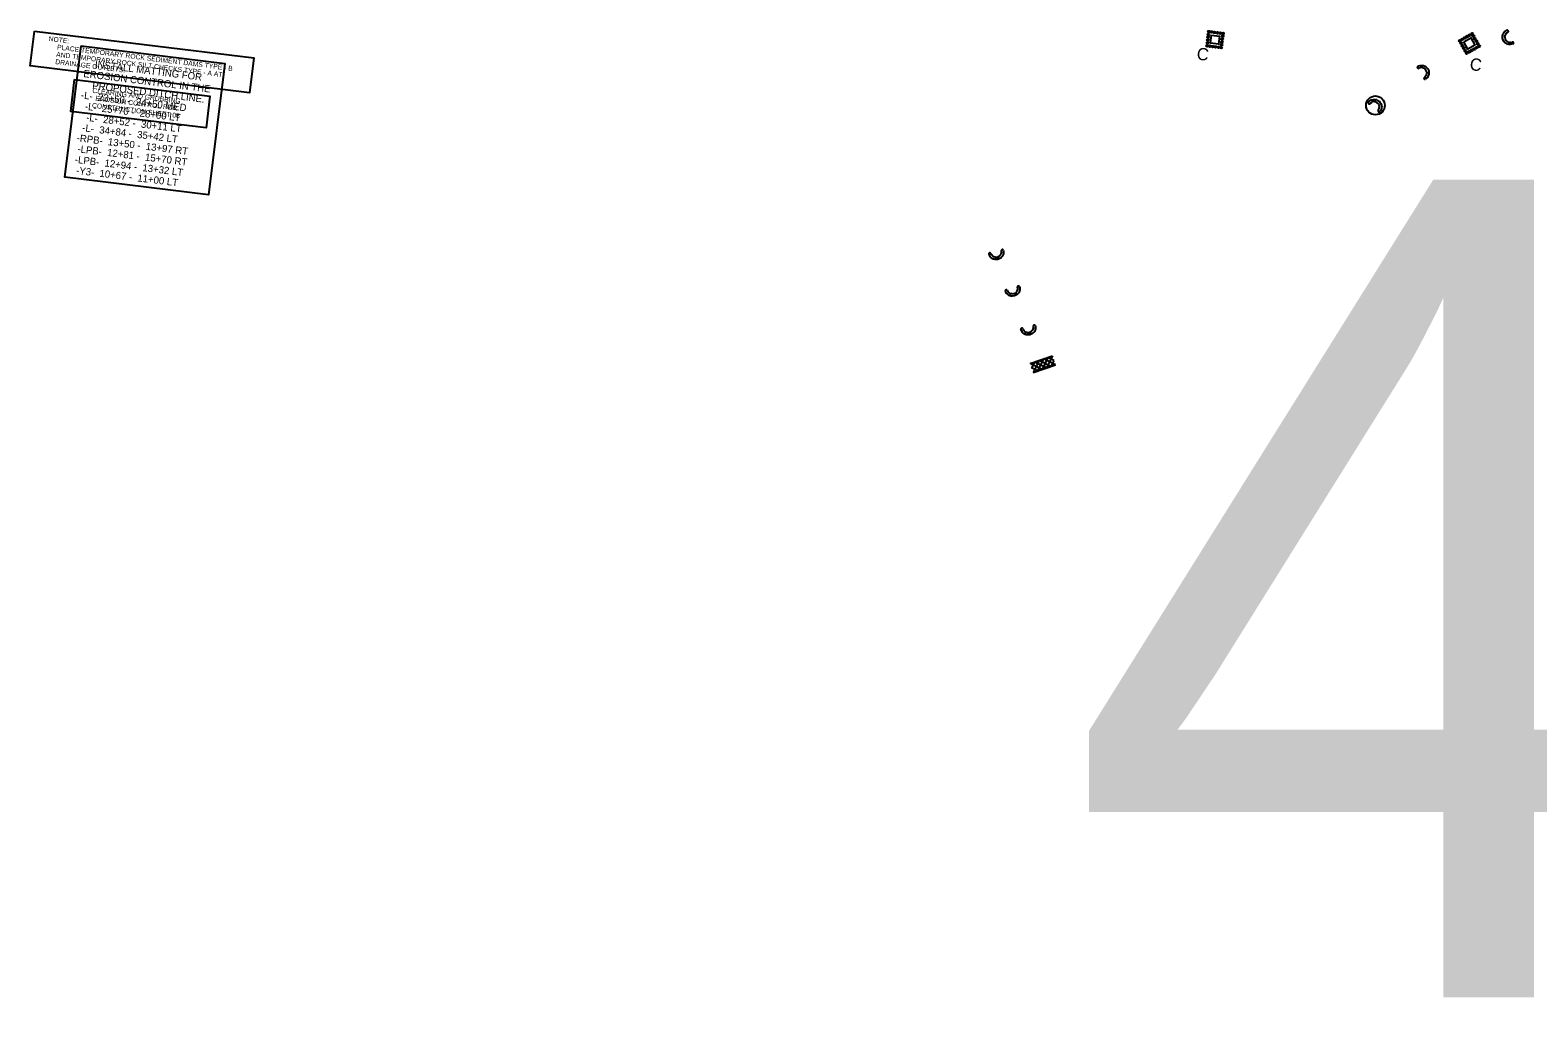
# Model space of a CAD drawing. Extents: x 2470000 to 2520000, y 340000 to 380000.
# Drawn here: x 2482139 to 2483984, y 364486 to 365683 of the extents above; entities that cross this region are included whole.
import ezdxf

# ---------------------------------------------------------------- set-up
doc = ezdxf.new("R2010")
doc.units = 0
for name, color, linetype in [('Coir Fiber Wattle Both CELL', 7, 'Continuous'), ('Coir Fiber Wattle with PAM Both CELL', 7, 'Continuous'), ('Construction Sheet Number Note CG CELL', 7, 'Continuous'), ('Matting in Proposed Ditchline Note Final CELL', 7, 'Continuous'), ('Prop Guardrail', 7, 'Continuous'), ('Prop Guardrail Anchor Unit CELL', 7, 'Continuous'), ('Prop Structure Anchor Unit CELL', 7, 'Continuous'), ('Rock Inlet Sediment Trap Type C CG CELL', 7, 'Continuous'), ('Rock Silt Check Type A Final CELL', 7, 'Continuous'), ('Scratch_Level_5', 7, 'Continuous'), ('Scratch_Level_6', 7, 'Continuous'), ('Sediment Dams and Silt Check Note CG CELL', 7, 'Continuous'), ('Wattle Final CELL', 7, 'Continuous')]:
    doc.layers.add(name, color=color, linetype=linetype)

# ---------------------------------------------------------------- blocks, each defined once
blk = doc.blocks.new('C3')
at = {"layer": 'Prop Guardrail'}
blk.add_text('C', height=0.3, dxfattribs=at).set_placement((-0.161, -0.136))
blk = doc.blocks.new('C2')
at = {"layer": 'Prop Guardrail Anchor Unit CELL'}
blk.add_text('C', height=0.3, dxfattribs=at).set_placement((-0.161, -0.136))
blk = doc.blocks.new('CGNT2')
at = {"layer": 'Sediment Dams and Silt Check Note CG CELL'}
blk.add_lwpolyline([(-2.704, 0.431), (2.704, 0.43125), (2.704, -0.43), (-2.704, -0.43)], close=True, dxfattribs=at)
for s, p in [('NOTE:', (-2.335, 0.231)), ('     PLACE TEMPORARY ROCK SEDIMENT DAMS TYPE - B', (-2.335, 0.05125)), ('     AND TEMPORARY ROCK SILT CHECKS TYPE - A AT', (-2.335, -0.129)), ('     DRAINAGE OUTLETS.', (-2.335, -0.309))]:
    blk.add_text(s, height=0.12, dxfattribs=at).set_placement(p)

msp = doc.modelspace()

# ---------------------------------------------------------------- linework, layer by layer
at = {"layer": 'Coir Fiber Wattle Both CELL'}
for p, q in [((2483943.2, 365674.5), (2483943.4, 365675.7)), ((2483943.2, 365674.5), (2483943.8, 365671.9)), ((2483943.5, 365676.8), (2483943.4, 365675.7)), ((2483943.5, 365676.8), (2483943.6, 365677)), ((2483944.4, 365678.2), (2483943.6, 365677)), ((2483943.8, 365671.9), (2483943.8, 365671.9)), ((2483943.8, 365671.9), (2483945.2, 365669.8)), ((2483945, 365679.2), (2483944.4, 365678.2)), ((2483945.6, 365679.6), (2483945, 365679.2)), ((2483945.2, 365669.8), (2483946.2, 365669.1)), ((2483946.9, 365680.5), (2483945.6, 365679.6)), ((2483946.2, 365669.1), (2483947.4, 365668.3)), ((2483947.4, 365668.3), (2483948.4, 365668.1)), ((2483948.4, 365668.1), (2483949.9, 365667.9)), ((2483950.2, 365668), (2483949.9, 365667.9)), ((2483950.2, 365668), (2483952, 365668.4)), ((2483839.7, 365637), (2483838, 365636.3)), ((2483839.7, 365637), (2483840, 365637.1)), ((2483841.5, 365637.1), (2483840, 365637.1)), ((2483842.5, 365637.1), (2483841.5, 365637.1)), ((2483843.8, 365636.4), (2483842.5, 365637.1)), ((2483844.9, 365635.9), (2483843.8, 365636.4)), ((2483844.8, 365625.1), (2483845.9, 365626.1)), ((2483846.6, 365634), (2483844.9, 365635.9)), ((2483845.9, 365626.1), (2483846.5, 365626.7)), ((2483846.5, 365626.7), (2483847, 365627.7)), ((2483846.6, 365634), (2483846.6, 365634)), ((2483847.6, 365631.5), (2483846.6, 365634)), ((2483847, 365627.7), (2483847.6, 365629)), ((2483847.6, 365631.5), (2483847.6, 365630.4)), ((2483847.6, 365629.2), (2483847.6, 365630.4)), ((2483847.6, 365629.2), (2483847.6, 365629))]:
    msp.add_line(p, q, dxfattribs=at)
for points in [[(2483953, 365666), (2483951.5, 365665.6), (2483949.8, 365665.2), (2483948.9, 365665.3), (2483947.9, 365665.5), (2483946.2, 365665.8), (2483946.1, 365665.8), (2483945.8, 365666), (2483945.7, 365666.1), (2483944.9, 365666.6), (2483944.3, 365667), (2483943.1, 365667.8), (2483942.5, 365668.6), (2483941.1, 365670.8), (2483941.1, 365670.8), (2483940.5, 365673.3), (2483940.3, 365674.3), (2483940.5, 365675.5), (2483940.5, 365675.7), (2483940.7, 365676.6), (2483940.8, 365677.4), (2483940.8, 365677.5), (2483940.9, 365677.9), (2483940.9, 365677.9), (2483941.8, 365679.1), (2483942.5, 365680.3), (2483942.9, 365680.9), (2483944.4, 365681.9), (2483945.7, 365682.8)], [(2483836.6, 365638.5), (2483838, 365639.1), (2483839.7, 365639.8), (2483840.6, 365639.8), (2483841.6, 365639.8), (2483843.4, 365639.7), (2483843.4, 365639.7), (2483843.8, 365639.5), (2483843.9, 365639.5), (2483844.7, 365639.1), (2483845.3, 365638.8), (2483846.7, 365638.2), (2483847.4, 365637.4), (2483849.1, 365635.6), (2483849.1, 365635.6), (2483850.1, 365633.1), (2483850.4, 365632.1), (2483850.4, 365631), (2483850.4, 365630.8), (2483850.4, 365629.8), (2483850.3, 365629.1), (2483850.3, 365628.9), (2483850.3, 365628.5), (2483850.3, 365628.5), (2483849.7, 365627.2), (2483849.1, 365626), (2483848.8, 365625.2), (2483847.5, 365624), (2483846.4, 365623)]]:
    msp.add_lwpolyline(points, dxfattribs=at)
for centre, radius, start, end in [((2483946.2, 365681.6), 1.33, 302.3767, 113.4893), ((2483952.5, 365667.2), 1.3, 293.4893, 113.4893), ((2483837.3, 365637.4), 1.3, 121.9646, 301.9646), ((2483845.6, 365624.1), 1.33, 130.852, 301.9646)]:
    msp.add_arc(centre, radius, start, end, dxfattribs=at)
at = {"layer": 'Coir Fiber Wattle with PAM Both CELL'}
for p, q in [((2483779.9, 365594.6), (2483778.4, 365593.4)), ((2483779.9, 365594.6), (2483780.1, 365594.8)), ((2483781.6, 365595.2), (2483780.1, 365594.8)), ((2483782.5, 365595.5), (2483781.6, 365595.2)), ((2483784, 365595.3), (2483782.5, 365595.5)), ((2483785.2, 365595.1), (2483784, 365595.3)), ((2483787.4, 365593.8), (2483785.2, 365595.1)), ((2483787.4, 365593.8), (2483787.4, 365593.8)), ((2483789, 365591.8), (2483787.4, 365593.8)), ((2483789, 365591.8), (2483789.4, 365590.6)), ((2483789.7, 365589.6), (2483789.4, 365590.6)), ((2483789.6, 365587.9), (2483789.8, 365589.4)), ((2483789.7, 365589.6), (2483789.8, 365589.4)), ((2483788.3, 365584.8), (2483789.1, 365586.1)), ((2483789.1, 365586.1), (2483789.5, 365586.8)), ((2483789.5, 365586.8), (2483789.6, 365587.9))]:
    msp.add_line(p, q, dxfattribs=at)
msp.add_lwpolyline([(2483776.5, 365595.1), (2483777.7, 365596.1), (2483779.1, 365597.2), (2483779.8, 365597.5), (2483780.8, 365597.8), (2483782.5, 365598.3), (2483782.6, 365598.3), (2483783, 365598.2), (2483783.1, 365598.2), (2483784, 365598.1), (2483784.7, 365598), (2483786.1, 365597.9), (2483787.1, 365597.3), (2483789.3, 365596.1), (2483789.3, 365596.1), (2483790.9, 365594), (2483791.6, 365593.2), (2483791.9, 365592.1), (2483792, 365591.9), (2483792.2, 365591), (2483792.4, 365590.3), (2483792.5, 365590.1), (2483792.6, 365589.8), (2483792.6, 365589.8), (2483792.4, 365588.3), (2483792.2, 365586.9), (2483792.1, 365586.1), (2483791.2, 365584.6), (2483790.5, 365583.2)], dxfattribs=at)
msp.add_circle((2483784.9, 365590.9), 11.5, dxfattribs=at)
for centre, radius, start in [((2483777.4, 365594.2), 1.3, 139.7087), ((2483789.5, 365584.1), 1.33, 148.5961)]:
    msp.add_arc(centre, radius, start, 319.7087, dxfattribs=at)
at = {"layer": 'Construction Sheet Number Note CG CELL'}
msp.add_lwpolyline([(2482193.6, 365622.4), (2482359.3, 365602), (2482354.5, 365563.3), (2482188.9, 365583.6)], close=True, dxfattribs=at)
at = {"layer": 'Matting in Proposed Ditchline Note Final CELL'}
msp.add_lwpolyline([(2482201.7, 365663.9), (2482377.3, 365642.3), (2482357.5, 365481.6), (2482181.9, 365503.2)], close=True, dxfattribs=at)
at = {"layer": 'Prop Structure Anchor Unit CELL'}
msp.add_lwpolyline([(2483893.1, 365668.5), (2483901.8, 365673.4), (2483906.7, 365664.7), (2483898, 365659.8)], close=True, dxfattribs=at)
for centre in [(2483888, 365669.9), (2483889.7, 365666.9), (2483891, 365671.7), (2483891.4, 365663.8), (2483894.1, 365673.4), (2483897.1, 365675.1), (2483900.2, 365676.8), (2483903.2, 365678.5), (2483904.9, 365675.4), (2483906.6, 365672.4), (2483908.4, 365669.3), (2483910.1, 365666.3), (2483911.8, 365663.2), (2483893.1, 365660.8), (2483894.8, 365657.7), (2483896.5, 365654.7), (2483899.6, 365656.4), (2483902.6, 365658.1), (2483905.7, 365659.8), (2483908.7, 365661.5)]:
    msp.add_circle(centre, 1.12, dxfattribs=at)
at = {"layer": 'Rock Silt Check Type A Final CELL'}
for p, q in [((2483362.4, 365275.2), (2483389.8, 365284.4)), ((2483367.8, 365276.9), (2483364.2, 365269.7)), ((2483373.4, 365278.9), (2483366.1, 365264.2)), ((2483382.6, 365269.8), (2483367.9, 365277)), ((2483378.9, 365280.7), (2483371.6, 365266.1)), ((2483388, 365271.6), (2483373.4, 365278.9)), ((2483384.3, 365282.6), (2483377.1, 365267.9)), ((2483393.5, 365273.5), (2483378.9, 365280.7)), ((2483389.8, 365284.4), (2483382.6, 365269.8)), ((2483391.7, 365279), (2483384.3, 365282.6)), ((2483391.7, 365279), (2483388, 365271.6)), ((2483377.1, 365267.9), (2483362.4, 365275.2)), ((2483371.6, 365266.1), (2483364.2, 365269.7)), ((2483366.1, 365264.2), (2483393.5, 365273.5))]:
    msp.add_line(p, q, dxfattribs=at)
at = {"layer": 'Scratch_Level_5'}
msp.add_lwpolyline([(2483584.4, 365676.9), (2483594.3, 365675.6), (2483593, 365665.7), (2483583.1, 365667)], close=True, dxfattribs=at)
for centre in [(2483581.2, 365681.1), (2483584.6, 365680.7), (2483588.1, 365680.2), (2483578.9, 365663.7), (2483579.4, 365667.2), (2483579.8, 365670.7), (2483580.3, 365674.2), (2483580.7, 365677.6), (2483582.4, 365663.3), (2483585.8, 365662.8), (2483589.3, 365662.4), (2483591.6, 365679.7), (2483592.8, 365661.9), (2483595, 365679.3), (2483596.7, 365665), (2483597.2, 365668.4), (2483597.6, 365671.9), (2483598.1, 365675.4), (2483598.5, 365678.8), (2483596.3, 365661.5)]:
    msp.add_circle(centre, 1.12, dxfattribs=at)
at = {"layer": 'Wattle Final CELL'}
for p, q in [((2483314.6, 365409.8), (2483315.2, 365408.4)), ((2483315.2, 365408.4), (2483315.5, 365407.7)), ((2483315.5, 365407.7), (2483316.4, 365406.9)), ((2483316.4, 365406.9), (2483317.4, 365406)), ((2483317.7, 365405.9), (2483317.4, 365406)), ((2483317.7, 365405.9), (2483318.7, 365405.6)), ((2483319.9, 365405.2), (2483318.7, 365405.6)), ((2483319.9, 365405.2), (2483322.5, 365405.4)), ((2483322.5, 365405.4), (2483324.8, 365406.4)), ((2483322.5, 365405.4), (2483322.5, 365405.4)), ((2483324.8, 365406.4), (2483325.6, 365407.3)), ((2483325.6, 365407.3), (2483326.6, 365408.4)), ((2483326.6, 365408.4), (2483327, 365409.3)), ((2483327, 365409.3), (2483327.4, 365410.7)), ((2483327.4, 365411.1), (2483327.3, 365412.9)), ((2483327.4, 365411.1), (2483327.4, 365410.7)), ((2483347.4, 365366.5), (2483347.2, 365368.4)), ((2483334.6, 365364.7), (2483335.3, 365363.3)), ((2483335.3, 365363.3), (2483335.6, 365362.6)), ((2483335.6, 365362.6), (2483336.5, 365361.9)), ((2483336.5, 365361.9), (2483337.6, 365361)), ((2483337.8, 365360.9), (2483337.6, 365361)), ((2483337.8, 365360.9), (2483338.9, 365360.6)), ((2483340.1, 365360.3), (2483338.9, 365360.6)), ((2483340.1, 365360.3), (2483342.7, 365360.6)), ((2483342.7, 365360.6), (2483345, 365361.8)), ((2483342.7, 365360.6), (2483342.7, 365360.6)), ((2483345, 365361.8), (2483345.8, 365362.7)), ((2483345.8, 365362.7), (2483346.7, 365363.8)), ((2483346.7, 365363.8), (2483347, 365364.7)), ((2483347, 365364.7), (2483347.4, 365366.2)), ((2483347.4, 365366.5), (2483347.4, 365366.2)), ((2483353.7, 365317.6), (2483354.3, 365316.2)), ((2483354.3, 365316.2), (2483354.7, 365315.5)), ((2483354.7, 365315.5), (2483355.5, 365314.7)), ((2483355.5, 365314.7), (2483356.6, 365313.7)), ((2483356.8, 365313.7), (2483356.6, 365313.7)), ((2483356.8, 365313.7), (2483357.8, 365313.3)), ((2483359, 365313), (2483357.8, 365313.3)), ((2483359, 365313), (2483361.6, 365313.2)), ((2483361.6, 365313.2), (2483363.9, 365314.2)), ((2483361.6, 365313.2), (2483361.6, 365313.2)), ((2483363.9, 365314.2), (2483364.8, 365315)), ((2483364.8, 365315), (2483365.8, 365316.1)), ((2483365.8, 365316.1), (2483366.1, 365317.1)), ((2483366.1, 365317.1), (2483366.6, 365318.5)), ((2483366.6, 365318.8), (2483366.4, 365320.6)), ((2483366.6, 365318.8), (2483366.6, 365318.5))]:
    msp.add_line(p, q, dxfattribs=at)
for points in [[(2483329.8, 365413.6), (2483329.9, 365412), (2483330.1, 365410.2), (2483329.8, 365409.4), (2483329.5, 365408.5), (2483328.9, 365406.8), (2483328.9, 365406.7), (2483328.6, 365406.4), (2483328.6, 365406.3), (2483327.9, 365405.6), (2483327.5, 365405.1), (2483326.5, 365404.1), (2483325.5, 365403.6), (2483323.2, 365402.5), (2483323.2, 365402.5), (2483320.6, 365402.4), (2483319.6, 365402.3), (2483318.5, 365402.7), (2483318.3, 365402.7), (2483317.4, 365403), (2483316.7, 365403.3), (2483316.5, 365403.3), (2483316.2, 365403.5), (2483316.2, 365403.5), (2483315, 365404.5), (2483314.1, 365405.4), (2483313.5, 365405.9), (2483312.7, 365407.5), (2483312, 365408.9)], [(2483349.6, 365369.1), (2483349.8, 365367.6), (2483350.1, 365365.8), (2483349.8, 365364.9), (2483349.6, 365364), (2483349.1, 365362.2), (2483349, 365362.2), (2483348.8, 365361.9), (2483348.7, 365361.8), (2483348.1, 365361.1), (2483347.7, 365360.6), (2483346.7, 365359.5), (2483345.8, 365359), (2483343.5, 365357.8), (2483343.5, 365357.8), (2483340.9, 365357.5), (2483339.9, 365357.4), (2483338.8, 365357.7), (2483338.6, 365357.8), (2483337.7, 365358.1), (2483337, 365358.3), (2483336.8, 365358.3), (2483336.4, 365358.4), (2483336.4, 365358.4), (2483335.3, 365359.4), (2483334.3, 365360.3), (2483333.6, 365360.8), (2483332.8, 365362.4), (2483332.1, 365363.7)], [(2483369, 365321.3), (2483369.1, 365319.7), (2483369.2, 365317.9), (2483369, 365317.1), (2483368.6, 365316.2), (2483368.1, 365314.5), (2483368, 365314.4), (2483367.7, 365314.1), (2483367.7, 365314.1), (2483367, 365313.3), (2483366.6, 365312.9), (2483365.6, 365311.8), (2483364.6, 365311.3), (2483362.3, 365310.3), (2483362.3, 365310.3), (2483359.7, 365310.1), (2483358.7, 365310.1), (2483357.6, 365310.4), (2483357.4, 365310.5), (2483356.5, 365310.8), (2483355.8, 365311.1), (2483355.6, 365311.1), (2483355.3, 365311.3), (2483355.3, 365311.3), (2483354.2, 365312.3), (2483353.2, 365313.2), (2483352.6, 365313.8), (2483351.8, 365315.3), (2483351.2, 365316.7)]]:
    msp.add_lwpolyline(points, dxfattribs=at)
for centre, radius, start, end in [((2483313.3, 365409.3), 1.33, 23.4306, 194.5433), ((2483328.5, 365413.3), 1.3, 14.5433, 194.5433), ((2483348.4, 365368.7), 1.3, 16.841, 196.841), ((2483333.4, 365364.1), 1.33, 25.7284, 196.841), ((2483352.5, 365317.1), 1.33, 23.0295, 194.1421), ((2483367.7, 365321), 1.3, 14.1421, 194.1421)]:
    msp.add_arc(centre, radius, start, end, dxfattribs=at)

# ---------------------------------------------------------------- block references
at = {"layer": 'Rock Inlet Sediment Trap Type C CG CELL', "xscale": 50.00000000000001, "yscale": 49.99999999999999, "rotation": -6.997703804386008}
msp.add_blockref('C2', (2483908.5, 365640), dxfattribs=at)
at = {"layer": 'Scratch_Level_5', "xscale": 49.99999999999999, "yscale": 50.00000000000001, "rotation": -6.997703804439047}
msp.add_blockref('C3', (2483574.5, 365652.8), dxfattribs=at)
at = {"layer": 'Sediment Dams and Silt Check Note CG CELL', "xscale": 50.00000000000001, "yscale": 50.00000000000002, "rotation": -6.9977038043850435}
msp.add_blockref('CGNT2', (2482276.1, 365644), dxfattribs=at)

# ---------------------------------------------------------------- texts
at = {"layer": 'Construction Sheet Number Note CG CELL'}
for s, p in [('CLEARING AND GRUBBING', (2482215.2, 365606.3)), ('CONSTRUCTION SHEET 06', (2482214.7, 365588.2)), ('EROSION CONTROL FOR', (2482218.8, 365596.8))]:
    msp.add_text(s, height=6, rotation=353.0023, dxfattribs=at).set_placement(p)
at = {"layer": 'Matting in Proposed Ditchline Note Final CELL'}
for s, p in [('INSTALL MATTING FOR ', (2482218.1, 365637.2)), ('EROSION CONTROL IN THE', (2482204, 365625.6)), ('-L-  23+50 -  24+50 MED', (2482201.1, 365599.4)), ('PROPOSED DITCH LINE.', (2482214.9, 365611)), ('-L-  25+70 -  28+00 LT', (2482205.9, 365585.6)), ('-L-  28+52 -  30+11 LT', (2482207.4, 365572.1)), ('-RPB-  13+50 -  13+97 RT', (2482195.8, 365547)), ('-L-  34+84 -  35+42 LT', (2482202.7, 365559.4)), ('-LPB-  12+81 -  15+70 RT', (2482196.8, 365533.6)), ('-LPB-  12+94 -  13+32 LT', (2482193.6, 365520.7)), ('-Y3-  10+67 -  11+00 LT', (2482195.2, 365507.2))]:
    msp.add_text(s, height=8.785, rotation=353.0023, dxfattribs=at).set_placement(p)
at = {"layer": 'Scratch_Level_6'}
msp.add_text('4386', height=1000, dxfattribs=at).set_placement((2483403.8, 364500))

doc.saveas('drawing.dxf')
